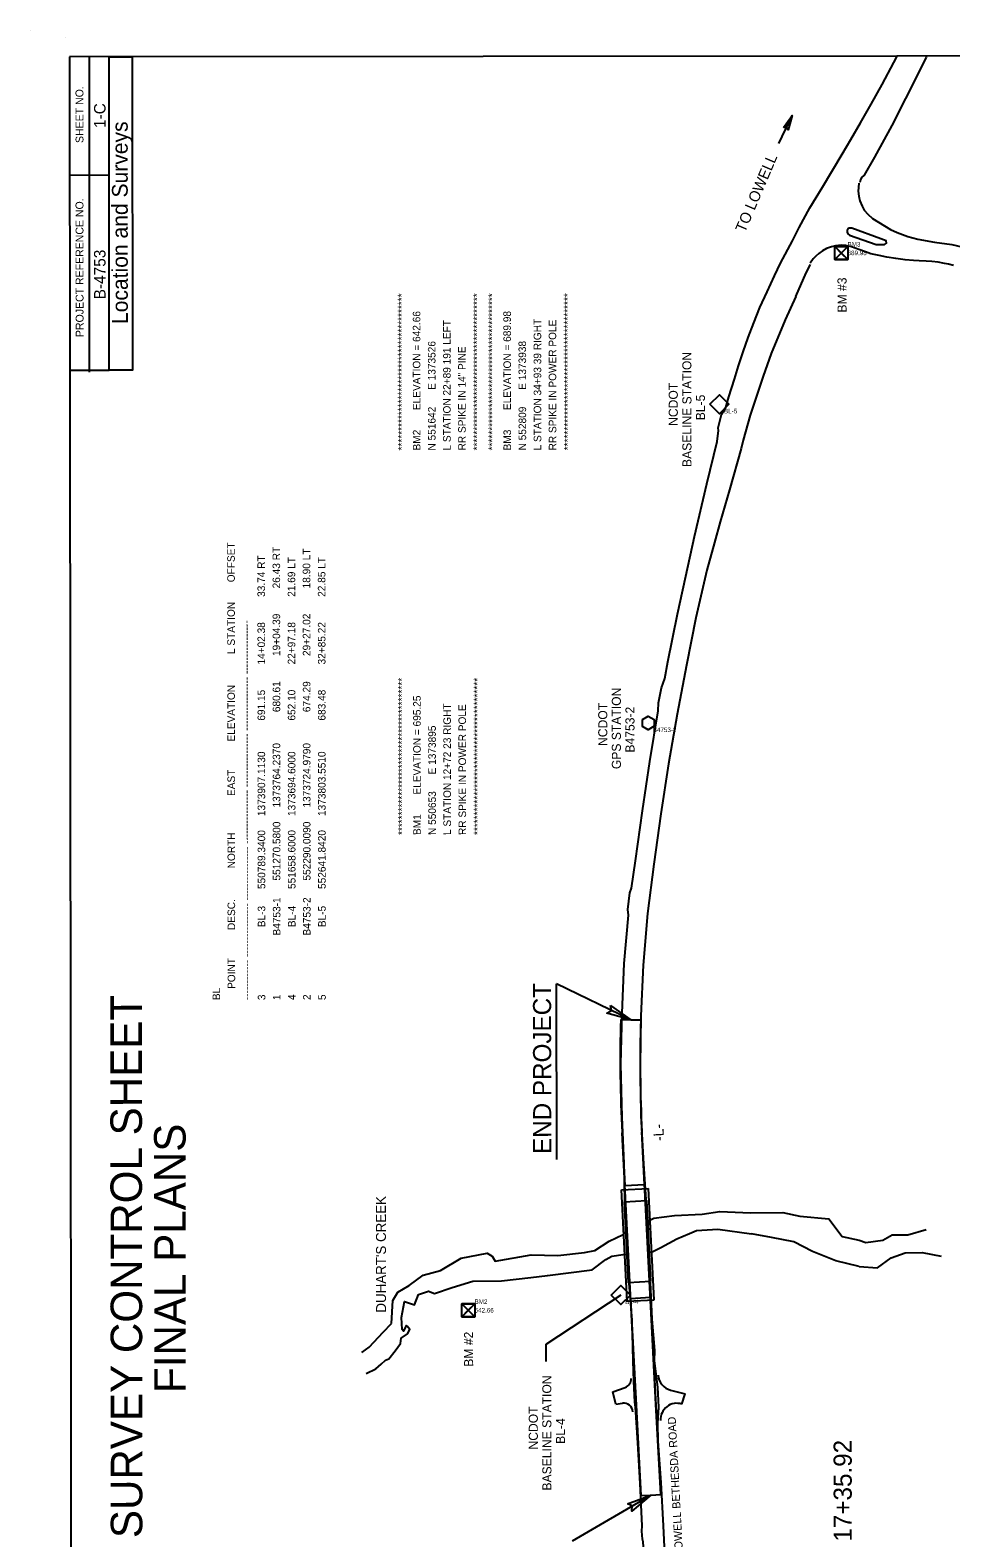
# Model space of a CAD drawing. Extents: x 1373043 to 1375788, y 550128 to 553055.
# Drawn here: x 1373043 to 1374059, y 551391 to 553055 of the extents above; entities that cross this region are included whole.
import ezdxf

# ---------------------------------------------------------------- set-up
doc = ezdxf.new("R2010")
doc.units = 0
for name, color, linetype in [('CTL Bench Mark CELL', 7, 'Continuous'), ('CTL Bench Mark Text', 7, 'Continuous'), ('CTL GPS Vertical CELL', 7, 'Continuous'), ('CTL GPS Vertical Text', 7, 'Continuous'), ('CTL Sheet Border CELL', 7, 'Continuous'), ('CTL Sheet Text', 7, 'Continuous'), ('CTL Supplemental Horizontal and Vertical CELL', 7, 'Continuous'), ('CTL Supplemental Horizontal and Vertical Leader', 7, 'Continuous'), ('CTL Supplemental Horizontal and Vertical Text', 7, 'Continuous'), ('Default', 7, 'Continuous'), ('Exist Hydro Jurisdictional Stream or Body of Water', 7, 'Continuous'), ('Exist Roads EOP', 7, 'Continuous'), ('Exist Roads EOP Other', 7, 'Continuous'), ('Exist Structure Major Deck Tunnel Box Culvert', 7, 'Continuous'), ('Prop EOT', 7, 'Continuous'), ('Prop Horizontal Alignment Station Label', 7, 'Continuous'), ('Prop North Arrow for Plan Sheets CELL', 7, 'Continuous'), ('Prop Roadway Bridge', 7, 'Continuous'), ('Prop Shade Light', 7, 'Continuous'), ('Prop Terminator CELL', 7, 'Continuous'), ('Scratch_Level_0', 7, 'Continuous')]:
    doc.layers.add(name, color=color, linetype=linetype)

msp = doc.modelspace()

# ---------------------------------------------------------------- linework, layer by layer
at = {"layer": 'CTL Bench Mark CELL'}
for p, q in [((1373938, 552808.9), (1373938, 552808.9)), ((1373526.3, 551641.8), (1373526.3, 551641.8))]:
    msp.add_line(p, q, dxfattribs=at)
for points in [[(1373930.8, 552816), (1373945.2, 552816), (1373945.2, 552801.7), (1373930.8, 552801.7)], [(1373519.1, 551649), (1373533.5, 551649), (1373533.5, 551634.6), (1373519.1, 551634.6)]]:
    msp.add_lwpolyline(points, close=True, dxfattribs=at)
for points in [[(1373945.2, 552816), (1373930.8, 552801.7), (1373938, 552808.8), (1373945.2, 552801.7), (1373930.8, 552816)], [(1373938, 552808.8), (1373945.2, 552816), (1373930.8, 552816), (1373938, 552808.8)], [(1373938, 552808.8), (1373930.8, 552801.7), (1373945.2, 552801.7), (1373938, 552808.8)], [(1373533.5, 551649), (1373519.1, 551634.6), (1373526.3, 551641.8), (1373533.5, 551634.6), (1373519.1, 551649)], [(1373526.3, 551641.8), (1373533.5, 551649), (1373519.1, 551649), (1373526.3, 551641.8)], [(1373526.3, 551641.8), (1373519.1, 551634.6), (1373533.5, 551634.6), (1373526.3, 551641.8)]]:
    msp.add_lwpolyline(points, dxfattribs=at)
at = {"layer": 'CTL GPS Vertical CELL'}
msp.add_line((1373724.9, 552290), (1373724.9, 552290), dxfattribs=at)
msp.add_lwpolyline([(1373718.5, 552293.8), (1373725, 552297.4), (1373731.5, 552293.8), (1373731.4, 552286.4), (1373724.9, 552282.6), (1373718.5, 552286.2)], close=True, dxfattribs=at)
at = {"layer": 'CTL Sheet Border CELL'}
for p, q in [((1373042.7, 553054.8), (1373042.7, 553054.8)), ((1373081.7, 553047), (1373081.7, 553047)), ((1373081.7, 553047), (1373081.7, 553047)), ((1373108.3, 552677.3), (1373108, 553025.3)), ((1373086.4, 552894.8), (1373129.8, 552894.9)), ((1373086.5, 552679.3), (1373130, 552679.3))]:
    msp.add_line(p, q, dxfattribs=at)
for points in [[(1373086.2, 553025.2), (1373088.5, 550416.5), (1374914.6, 550418.2), (1374912.2, 553026.9)], [(1373130, 552679.3), (1373129.7, 553025.3), (1373155.3, 553025.3), (1373155.6, 552679.4)]]:
    msp.add_lwpolyline(points, close=True, dxfattribs=at)
at = {"layer": 'CTL Supplemental Horizontal and Vertical CELL'}
for p, q in [((1373803.6, 552641.8), (1373803.6, 552641.8)), ((1373694.6, 551658.6), (1373694.6, 551658.6))]:
    msp.add_line(p, q, dxfattribs=at)
for points in [[(1373793.1, 552641.9), (1373803.6, 552652.4), (1373814.1, 552641.9), (1373803.6, 552631.4)], [(1373684.2, 551658.6), (1373694.7, 551669.1), (1373705.2, 551658.6), (1373694.7, 551648.1)]]:
    msp.add_lwpolyline(points, close=True, dxfattribs=at)
at = {"layer": 'CTL Supplemental Horizontal and Vertical Leader'}
msp.add_lwpolyline([(1373694.6, 551658.6), (1373612, 551604), (1373612, 551585.4)], dxfattribs=at)
at = {"layer": 'Default'}
msp.add_line((1373869, 552929.7), (1373883.7, 552960.6), dxfattribs=at)
at = {"layer": 'Exist Hydro Jurisdictional Stream or Body of Water'}
for points in [[(1373724.6, 551731.6), (1373727.4, 551731.7), (1373727.3, 551734.8), (1373726.1, 551740.8), (1373731.2, 551743.5), (1373754, 551746.3), (1373784.4, 551747.8), (1373804, 551750.9), (1373837.8, 551749.5)], [(1373837.8, 551749.5), (1373873.4, 551749.8), (1373892.4, 551745.5), (1373924.4, 551742.8), (1373939, 551723.2), (1373957.8, 551719.2)], [(1373726, 551706), (1373730.2, 551706.8), (1373739, 551711.2), (1373756.5, 551720.5), (1373770.6, 551726.5), (1373778.4, 551729.7), (1373801.9, 551731.3), (1373838.9, 551726.2)], [(1373957.8, 551719.2), (1373965.2, 551716.5), (1373984.1, 551719.1), (1373994.3, 551725.1), (1374011.7, 551725.2), (1374031.8, 551730.8)], [(1373654.5, 551705.7), (1373666, 551707.8), (1373681.9, 551718), (1373697.2, 551725.4), (1373700.4, 551728.8)], [(1373957.9, 551690.2), (1373932.1, 551696.5), (1373906.1, 551706.6), (1373885.6, 551717.4), (1373860.9, 551722), (1373838.9, 551726.2)], [(1373441.5, 551627.2), (1373443.2, 551652.5), (1373448.6, 551661.9), (1373461.1, 551669.2), (1373476.5, 551680.4), (1373495.6, 551685.8), (1373518.5, 551699.4), (1373547, 551704.9), (1373552.5, 551701.5), (1373556, 551696), (1373595.9, 551702.9), (1373625.2, 551702.4), (1373654.5, 551705.7)], [(1373662.9, 551686.3), (1373678, 551697.8), (1373684.8, 551701.4), (1373697.3, 551703.3), (1373701.6, 551703.6)], [(1373957.9, 551690.2), (1373977.9, 551688.5), (1373993, 551699.6), (1374008.5, 551705.2), (1374027.2, 551705.4), (1374048.3, 551701.6)], [(1373452.7, 551633.9), (1373455.9, 551651.3), (1373466.8, 551647.9), (1373471.2, 551659.1), (1373482.3, 551662.9), (1373488.9, 551660.3), (1373508.5, 551667.1), (1373531.2, 551673.8), (1373562.8, 551674.2), (1373595.3, 551677.8), (1373613.7, 551680.2), (1373662.9, 551686.3)], [(1373413.6, 551572.1), (1373424.2, 551577), (1373430.2, 551582.4), (1373435.1, 551586.6), (1373438.7, 551588.2), (1373445.5, 551597), (1373451.4, 551605.2), (1373452.3, 551611.1), (1373459.1, 551615.8), (1373461.8, 551620.6), (1373458.9, 551624.1), (1373457.8, 551625.1), (1373454.8, 551618.8), (1373453.2, 551620.4), (1373452.7, 551633.9)], [(1373408.8, 551595.3), (1373416.9, 551601), (1373432.5, 551617.6), (1373441.5, 551627.2)]]:
    msp.add_lwpolyline(points, dxfattribs=at)
at = {"layer": 'Exist Roads EOP'}
for points in [[(1373856.1, 552766), (1373864.2, 552783.7), (1373870.8, 552797.5), (1373884.1, 552822.4), (1373891.4, 552837.1), (1373903.5, 552858.7), (1373917.5, 552881.5), (1373938.9, 552917.9), (1373948.6, 552933.9), (1373959.4, 552952.5), (1373971.1, 552972.9), (1373983.1, 552994.8), (1373996.2, 553019.2), (1373999.7, 553026.1)], [(1374032.3, 553026.1), (1374031.6, 553024.6), (1374008.8, 552979.4), (1373993.7, 552949.5), (1373974.7, 552914.7), (1373963.5, 552894.6), (1373960.5, 552892), (1373959.3, 552889.5), (1373958.4, 552886.5)], [(1373887.8, 552760.7), (1373899.4, 552786.8), (1373904.2, 552796)], [(1373801.1, 552600.8), (1373802.5, 552612.7), (1373802.2, 552615.7), (1373805.9, 552630.6), (1373810.6, 552638.3), (1373814.1, 552649.9), (1373820.1, 552669.5), (1373824.7, 552684.4), (1373829.6, 552699.6), (1373835.4, 552715.6), (1373841.7, 552731.9), (1373848.3, 552748.7), (1373856.1, 552766)], [(1373887.8, 552760.7), (1373876.1, 552735), (1373860.6, 552698), (1373851.9, 552672.9), (1373837.6, 552629.9), (1373829.9, 552602.1), (1373827.5, 552592.9)], [(1373699.2, 551761.7), (1373698.3, 551803.9), (1373696.1, 551855), (1373694.8, 551913.4), (1373696, 551969.7), (1373698.3, 552024.6), (1373703.3, 552077.8), (1373702.5, 552084), (1373704.6, 552102.6), (1373706.6, 552107.7), (1373710.9, 552137.8), (1373718.5, 552192.9), (1373726.9, 552247.5), (1373735.9, 552303.5), (1373736.2, 552312.3), (1373739.6, 552328.9), (1373741.5, 552334.1), (1373743.1, 552339.3), (1373746.6, 552357.4), (1373757.2, 552410.1), (1373768.9, 552463.9), (1373776, 552495.7), (1373789.5, 552553.9), (1373801.1, 552600.8)], [(1373827.5, 552592.9), (1373814.6, 552547.4), (1373804.3, 552512.1), (1373798, 552489.4), (1373789.7, 552458.8), (1373777.5, 552406.1), (1373767.1, 552353.7), (1373756.9, 552299.7), (1373747.4, 552244.8), (1373738.9, 552189.8), (1373731, 552134.3), (1373724.3, 552079.8), (1373719.4, 552022.6), (1373716.6, 551966.9), (1373715.9, 551912.1), (1373716.7, 551856.4), (1373719.9, 551803.4), (1373722.4, 551763.9)], [(1373735, 551213.3), (1373728.5, 551261.7), (1373727, 551263.3), (1373724.7, 551285.1), (1373725.6, 551287.7), (1373724.4, 551307.7), (1373721.1, 551358.8), (1373719.5, 551386.1), (1373718.5, 551389.1), (1373718, 551398.1), (1373718.1, 551403.8), (1373716.2, 551450.5), (1373713.5, 551495.5), (1373711, 551534.9), (1373710, 551540.4), (1373708.9, 551563.6), (1373708.4, 551585.9), (1373707.2, 551630.9), (1373704, 551671.6)], [(1373727.2, 551672.9), (1373729, 551632.1), (1373732, 551597.2), (1373731.6, 551586.1), (1373735.2, 551557), (1373736.3, 551535), (1373735.3, 551516.7), (1373735.7, 551497.3), (1373738.7, 551451.7), (1373741.3, 551403.7), (1373743.8, 551357.5), (1373746.4, 551308.8), (1373750.3, 551263.4), (1373757.4, 551217), (1373769.8, 551165.7), (1373783.5, 551119.3), (1373798.8, 551074.4), (1373816.6, 551024.8), (1373831.9, 550981.3), (1373844.7, 550944.9), (1373863.5, 550887)]]:
    msp.add_lwpolyline(points, dxfattribs=at)
at = {"layer": 'Exist Roads EOP Other'}
for points in [[(1373957.4, 552885.8), (1373956.9, 552881.2), (1373956.8, 552877.1), (1373957.3, 552871.4), (1373958.6, 552866.5), (1373961.1, 552860.5), (1373963.3, 552856.2), (1373967.2, 552851.6), (1373972.6, 552846.9), (1373979.2, 552842.9), (1373992.3, 552834.8), (1373999.6, 552831.3), (1374011.4, 552827), (1374022.5, 552824.1), (1374040.8, 552820.9), (1374060.1, 552818.1), (1374071.3, 552815.5), (1374081.4, 552811.9), (1374092.9, 552807), (1374101, 552801.9), (1374113, 552794.7), (1374123.5, 552786.9), (1374133.8, 552778.9), (1374140.9, 552773.4)], [(1373981.7, 552824.3), (1373949.7, 552836.2), (1373948.2, 552836.3), (1373946.7, 552836.1), (1373945.2, 552835.4), (1373944.4, 552833.9), (1373944.4, 552831.8), (1373945.2, 552830.1), (1373947.3, 552828.5), (1373976.5, 552818.2), (1373985.8, 552818.2), (1373988, 552819.6), (1373987.6, 552822.4), (1373981.7, 552824.3)], [(1374061.8, 552795), (1374056.4, 552796.5), (1374052.1, 552797.3), (1374045.1, 552798.5), (1374038, 552799.4), (1374031.8, 552799.8), (1374024.1, 552800.3), (1374017.6, 552800.6), (1374008.6, 552801.4), (1373998.3, 552802.8), (1373988.4, 552804.2), (1373979.7, 552805.9), (1373970.7, 552808), (1373964.7, 552810.1), (1373957.5, 552812.7), (1373949.2, 552815.7), (1373943.1, 552817), (1373937.9, 552817.3), (1373931.5, 552816.7), (1373927.2, 552815.7), (1373921.9, 552813.7), (1373917.3, 552811.1), (1373913.2, 552808.1), (1373909.8, 552805.3), (1373907.1, 552802.2), (1373903.7, 552797.7)]]:
    msp.add_lwpolyline(points, dxfattribs=at)
at = {"layer": 'Exist Structure Major Deck Tunnel Box Culvert'}
msp.add_lwpolyline([(1373727.6, 551673.5), (1373703.1, 551672), (1373698.8, 551761.4), (1373723, 551763), (1373727.6, 551673.5)], dxfattribs=at)
at = {"layer": 'Prop EOT'}
for p, q in [((1373694.6, 551962.6), (1373716.6, 551961.9)), ((1373711.6, 551537.1), (1373696, 551837.8)), ((1373733.5, 551538.3), (1373718, 551838.9)), ((1373738.7, 551438.4), (1373718, 551838.9)), ((1373685.8, 551551.7), (1373699.5, 551556.7)), ((1373689.1, 551538.2), (1373685.8, 551551.7)), ((1373749.6, 551553.7), (1373765.8, 551549.7)), ((1373762, 551538.2), (1373765.8, 551549.7)), ((1373689.1, 551538.2), (1373696.5, 551539.2)), ((1373711.6, 551537.1), (1373716.7, 551437.3)), ((1373716.7, 551437.3), (1373727.7, 551437.8)), ((1373727.7, 551437.8), (1373738.7, 551438.4))]:
    msp.add_line(p, q, dxfattribs=at)
for centre, radius, start, end in [((1375240, 551917.6), 1546, 178.3325, 182.9585), ((1375240, 551917.6), 1524, 178.3325, 182.9585), ((1373696.1, 551566.1), 10, 290.0644, 2.9585), ((1373753.9, 551571.2), 18, 182.9585, 256.2723), ((1373698, 551529.3), 10, 2.9585, 98.1594), ((1373756.5, 551521.1), 18, 72.0149, 182.9585)]:
    msp.add_arc(centre, radius, start, end, dxfattribs=at)
at = {"layer": 'Prop Horizontal Alignment Station Label'}
for p, q in [((1373705.6, 551962.3), (1373623.8, 552002.2)), ((1373624, 551808.2), (1373623.8, 552002.2)), ((1373641.2, 551387.2), (1373727.7, 551437.8))]:
    msp.add_line(p, q, dxfattribs=at)
at = {"layer": 'Prop North Arrow for Plan Sheets CELL'}
msp.add_lwpolyline([(1373874.2, 552947.2), (1373883.7, 552960.6), (1373879.3, 552944.7), (1373877.6, 552947.8)], close=True, dxfattribs=at)
at = {"layer": 'Prop Roadway Bridge'}
for p, q in [((1373695.3, 551774.6), (1373725.3, 551776.2)), ((1373701.6, 551651.8), (1373695.3, 551774.6)), ((1373731.6, 551653.3), (1373725.3, 551776.2)), ((1373701.6, 551651.8), (1373731.6, 551653.3))]:
    msp.add_line(p, q, dxfattribs=at)
at = {"layer": 'Prop Shade Light'}
for points in [[(1373716.6, 551961.9), (1373705.6, 551962.3), (1373694.6, 551962.6)], [(1373696, 551837.8), (1373699.1, 551779.4)], [(1373699.1, 551779.4), (1373721, 551780.5), (1373718, 551838.9)], [(1373727.5, 551655.7), (1373705.5, 551654.5), (1373711.6, 551537.1), (1373716.7, 551437.3), (1373727.7, 551437.8), (1373738.7, 551438.4), (1373733.5, 551538.3), (1373727.5, 551655.7)]]:
    msp.add_lwpolyline(points, dxfattribs=at)
for radius in [1546, 1524]:
    msp.add_arc((1375240, 551917.6), radius, 178.3325, 182.9585, dxfattribs=at)
at = {"layer": 'Prop Terminator CELL'}
for points in [[(1373683.4, 551978.3), (1373705.6, 551962.3), (1373679.1, 551969.8), (1373684.3, 551972.7)], [(1373702.1, 551428.2), (1373727.7, 551437.8), (1373706.7, 551420), (1373707.3, 551425.9)]]:
    msp.add_lwpolyline(points, close=True, dxfattribs=at)

# ---------------------------------------------------------------- texts
at = {"layer": 'CTL Bench Mark Text'}
for s, p in [('BM #3', (1373943.9, 552743.1)), ('BM #2', (1373531.7, 551579.5))]:
    msp.add_text(s, height=10, rotation=90.051, dxfattribs=at).set_placement(p)
at = {"layer": 'CTL GPS Vertical Text'}
for s, p in [('GPS STATION', (1373694.8, 552239.1)), ('NCDOT', (1373679.8, 552264.7)), ('B4753-2', (1373709.8, 552257.4))]:
    msp.add_text(s, height=10, rotation=90.051, dxfattribs=at).set_placement(p)
at = {"layer": 'CTL Sheet Border CELL'}
for s, height, p in [('SHEET NO.', 8.7, (1373101.5, 552930.2)), ('1-C', 12.7, (1373125.9, 552946.8)), ('Location and Surveys', 17.392, (1373150.5, 552730.4)), ('PROJECT REFERENCE NO.', 8.696, (1373101.6, 552716)), ('B-4753', 12.7, (1373125.9, 552757.7)), ('SURVEY CONTROL SHEET', 34.783, (1373166.5, 551390.3)), ('FINAL PLANS', 34.783, (1373214.5, 551550.5))]:
    msp.add_text(s, height=height, rotation=90.0509, dxfattribs=at).set_placement(p)
at = {"layer": 'CTL Sheet Text'}
for s, height, p in [('****************************************', 8.333, (1373456.9, 552590.8)), ('****************************************', 8.333, (1373540.2, 552590.9)), ('****************************************', 8.333, (1373556.9, 552590.9)), ('****************************************', 8.333, (1373640.2, 552591)), ('BM2       ELEVATION = 642.66', 8.333, (1373473.5, 552590.8)), ('L STATION 22+89 191 LEFT', 8.333, (1373506.9, 552590.8)), ('BM3       ELEVATION = 689.98', 8.333, (1373573.5, 552590.9)), ('L STATION 34+93 39 RIGHT', 8.333, (1373606.9, 552590.9)), ('RR SPIKE IN POWER POLE', 8.333, (1373623.5, 552590.9)), ('N 551642      E 1373526', 8.333, (1373490.2, 552590.8)), ('RR SPIKE IN 14" PINE', 8.333, (1373523.5, 552590.9)), ('N 552809      E 1373938', 8.333, (1373590.2, 552590.9)), ('    POINT          DESC.           NORTH             EAST          ELEVATION           L STATION       OFFSET', 8.3333, (1373269, 551984.1)), ('1                     B4753-1      551270.5800     1373764.2370           680.61         19+04.39         26.43 RT', 8.3333, (1373319, 551984.2)), ('2                     B4753-2      552290.0090     1373724.9790           674.29         29+27.02         18.90 LT', 8.3333, (1373352.3, 551984.2)), ('3                        BL-3      550789.3400     1373907.1130           691.15         14+02.38         33.74 RT', 8.3333, (1373302.3, 551984.1)), ('4                        BL-4      551658.6000     1373694.6000           652.10         22+97.18         21.69 LT', 8.3333, (1373335.7, 551984.2)), ('5                        BL-5      552641.8420     1373803.5510           683.48         32+85.22         22.85 LT', 8.3333, (1373369, 551984.2)), ('------------ ---------------- ---------------- ---------------- ---------------- ---------------- ----------------', 8.3333, (1373285.7, 551984.1)), ('****************************************', 8.333, (1373457.2, 552166.4)), ('****************************************', 8.333, (1373540.6, 552166.4)), ('BM1       ELEVATION = 695.25', 8.333, (1373473.9, 552166.4)), ('L STATION 12+72 23 RIGHT', 8.333, (1373507.2, 552166.4)), ('RR SPIKE IN POWER POLE', 8.333, (1373523.9, 552166.4)), ('N 550653      E 1373895', 8.333, (1373490.6, 552166.4)), ('BL', 8.33, (1373252.3, 551984.1))]:
    msp.add_text(s, height=height, rotation=90.0509, dxfattribs=at).set_placement(p)
at = {"layer": 'CTL Supplemental Horizontal and Vertical Text'}
for s, p in [('BASELINE STATION', (1373772.7, 552572.6)), ('NCDOT', (1373757.6, 552618)), ('BL-5', (1373787.6, 552624.2)), ('BASELINE STATION', (1373618.1, 551442.8)), ('NCDOT', (1373603.1, 551488.1)), ('BL-4', (1373633.1, 551494.3))]:
    msp.add_text(s, height=10, rotation=90.051, dxfattribs=at).set_placement(p)
at = {"layer": 'Default'}
for s, height, rotation, p in [('TO LOWELL', 12, 66.8658, (1373831.7, 552830.6)), ("DUHART'S CREEK", 11, 90.0509, (1373435.5, 551639.2)), ('SR 2439 LOWELL BETHESDA ROAD  ', 8.889, 93.0397, (1373766, 551322))]:
    msp.add_text(s, height=height, rotation=rotation, dxfattribs=at).set_placement(p)
at = {"layer": 'Prop Horizontal Alignment Station Label'}
for s, height, rotation, p in [('END PROJECT', 20, 90.0509, (1373617.9, 551814.3)), ('-L-', 11.37, 92.9763, (1373742.5, 551828.9)), ('-L- PC STA 17+35.92', 20, 90.0509, (1373949.8, 551242.3))]:
    msp.add_text(s, height=height, rotation=rotation, dxfattribs=at).set_placement(p)
at = {"layer": 'Scratch_Level_0'}
for s, p in [('BM3', (1373945, 552815.9)), ('689.98', (1373945, 552806.4)), ('BL-5', (1373808.6, 552631.8)), ('B4753-2', (1373730, 552280)), ('BM2', (1373533.3, 551648.8)), ('BL-4', (1373699.6, 551648.6)), ('642.66', (1373533.3, 551639.3))]:
    msp.add_text(s, height=5, dxfattribs=at).set_placement(p)

doc.saveas('drawing.dxf')
